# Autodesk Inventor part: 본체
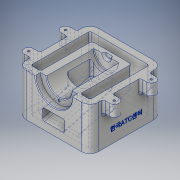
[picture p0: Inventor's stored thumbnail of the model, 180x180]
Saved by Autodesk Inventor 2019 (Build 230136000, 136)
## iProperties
Created: 2022-03
Part Number: 본체
Material: 알루미늄 6061
Document SubType Name: Modeling
Designer: LINE501-4
Density: 2.7 g/cm^3
Appearance: 알루미늄 - 평지
Mass: 1024.24 g
Surface Area: 844.702 cm^2
Volume: 379.349 cm^3
Author: LINE501-4
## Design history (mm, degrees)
sketch "스케치1"
  geometry: L1 (42, -55)-(-42, -55); L2 (-55, -42)-(-55, 42); L3 (-42, 55)-(42, 55); L4 (55, 42)-(55, -42); L5 (55, -55)-(-55, 55); L6 (-55, -55)-(55, 55); L7 (-42, -45)-(42, -45); L8 (45, -42)-(45, 42); L9 (-45, 42)-(-45, -42) reference; L10 (30, 0)-(30, 45); L11 (30, 45)-(30, -33); L12 (30, -33)-(-30, -33) reference; L13 (-30, -33)-(-30, 45) reference; L14 (42, 45)-(30, 45) reference; L15 (-30, 45)-(-42, 45) reference; A1 r 13 centre (42, -42) between (42, -55) and (55, -42); A2 r 13 centre (-42, -42) between (-55, -42) and (-42, -55); A3 r 13 centre (-42, 42) between (-42, 55) and (-55, 42); A4 r 13 centre (42, 42) between (55, 42) and (42, 55); A5 r 3 centre (42, -42) between (42, -45) and (45, -42); A6 r 3 centre (42, 42) between (45, 42) and (42, 45); A7 r 3 centre (-42, 42) between (-42, 45) and (-45, 42); A8 r 3 centre (-42, -42) between (-45, -42) and (-42, -45); 1 further point
  constraints: 30 end point, 16 point on circle, 8 centre point, 8 point on line, 8 tangent, 7 perpendicular, 5 parallel, 4 horizontal, 3 equal radius, 3 vertical, 2 midpoint, 5 other
  dimensions: "d0" = 110 distance of L5.end L6.end; "d1" = 110 distance of L6.start L5.end; "d2" = 13 radius of A1; "d3" = 10 distance between parallel lines of L1 L7; "d6" = 60 distance of L11.end L12.end
extrude "돌출1" new body sketch "스케치1" distance "d7" = 65; taper "d8" = 0 deg
sketch "스케치2"
  geometry: L1 (-55, -42)-(-55, 42) reference; L2 (-65, 21)-(-55, 21) reference; L3 (-65, 35)-(-55, 35); L4 (-65, -35)-(-55, -35) reference; L5 (-65, -21)-(-55, -21); L6 (55, -42)-(55, 42) reference; L7 (65, 21)-(55, 21) reference; L8 (65, 35)-(55, 35) reference; L9 (65, -21)-(55, -21) reference; L10 (65, -35)-(55, -35) reference; A1 r 13 centre (-42, 42) between (-42, 55) and (-55, 42) reference; A2 r 7 centre (-65, 28) between (-65, 35) and (-65, 21); A3 r 7 centre (-65, -28) between (-65, -21) and (-65, -35); A4 r 7 centre (65, -28) between (65, -35) and (65, -21); A5 r 7 centre (65, 28) between (65, 21) and (65, 35); 1 further point
  constraints: 16 end point, 8 point on circle, 8 point on line, 7 horizontal, 7 perpendicular, 4 centre point, 4 tangent, 4 other
  dimensions: "d13" = 14 diameter of A2; "d15" = 14 diameter of A3; "d18" = 14 diameter of A4; "d19" = 14 diameter of A5
extrude "돌출2" join sketch "스케치2" distance "d20" = 20; taper "d21" = 0 deg
sketch "스케치3"
  geometry: A1 r 7 centre (-65, 28) between (-65, 35) and (-65, 21) reference; A2 r 7 centre (-65, -28) between (-65, -21) and (-65, -35) reference; A3 r 7 centre (65, -28) between (65, -35) and (65, -21) reference; A4 r 7 centre (65, 28) between (65, 21) and (65, 35) reference; 5 further points
  constraints: 4 coincident
hole "구멍1" sketch "스케치3" at (-65, 28), (-65, -28), (65, -28), (65, 28) diameter "d22" = 3.242; stored, may be unused: countersink angle "d26" = 90 deg, drill point angle "d28" = 118 deg; dims "d23" = 9, "d24" = 4, "d25" = 2, "d27" = 11
sketch "스케치4"
  geometry: L1 (0, 65)-(84, 65) reference; L2 (34.5, 65)-(49.5, 65); C1 r 28 at (42, 65); C2 r 19 at (42, 65); A1 r 7.5 centre (42, 65) between (34.5, 65) and (49.5, 65); 1 further point
  constraints: 3 centre point, 2 coincident, 2 end point, 2 point on circle, 2 point on line, 1 midpoint
  dimensions: "d29" = 56 diameter of C1; "d30" = 38 diameter of C2; "d35" = 15 diameter of A1
extrude "돌출3" cut sketch "스케치4" distance "d31" = 8; taper "d32" = 0 deg
extrude "돌출4" cut sketch "스케치4" distance "d33" = 80; taper "d34" = 0 deg
extrude "돌출5" cut sketch "스케치4" distance "d36" = 84; taper "d37" = 0 deg
sketch "스케치5"
  geometry: L1 (65, -25)-(65, -29) reference; L2 (57.5, -25)-(57.5, -29) reference; L3 (57.5, -25)-(59.809, -29); L4 (57.5, -29)-(65, -29) reference; L5 (57.5, -25)-(62.119, -25); L6 (59.809, -29)-(57.5, -29); L7 (57.5, -29)-(57.5, -25); L8 (65, -25)-(65, -29); 1 further point
  constraints: 10 end point, 3 collinear, 1 equal length, 1 horizontal, 1 point on line
  dimensions: "d38" = 60 deg angle of L3 L5
revolve "회전1" sketch "스케치5" stored, may be unused: angle "d39" = 90 deg
extrude "돌출6" cut sketch "스케치4" distance "d40" = 84; taper "d41" = 0 deg
sketch "스케치7"
  geometry: L1 (42, -55)-(-42, -55) reference; L2 (0, -55)-(0, -19); L3 (0, -19)-(0, 0); L4 (-17, -19)-(17, -19); L5 (17, -19)-(17, 19); L6 (17, 19)-(-17, 19); L7 (-17, 19)-(-17, -19); L8 (-17, -19)-(17, 19); L9 (17, -19)-(-17, 19)
  constraints: 16 end point, 3 midpoint, 2 parallel, 1 collinear, 1 horizontal, 1 perpendicular, 1 vertical
  dimensions: "d44" = 36 distance of L2.start L2.end; "d45" = 19 distance of L2.end L3.end (derived); "d46" = 34 distance of L6.end L5.end; "d47" = 38 distance of L5.end L4.end
extrude "돌출7" cut sketch "스케치7" distance "d50" = 30; taper "d51" = 0 deg
sketch "스케치10"
  geometry: L1 (0, -33)-(65, -33) reference; L2 (0, -33)-(30, -33); L3 (30, -33)-(9.1, 45); L4 (31.425, -19)-(11.597, 55) reference; L5 (49.025, -19)-(29.197, 55); L6 (56.515, -19)-(35, -19) reference; L7 (56.515, -19)-(35, -19) reference; L8 (49.025, -19)-(31.425, -19); L9 (0, 55)-(65, 55) reference; L10 (0, 45)-(9.1, 45); L11 (0, 45)-(65, 45) reference; L12 (0, -33)-(0, 45) reference; L13 (0, -33)-(0, 45); 1 further point
  constraints: 14 end point, 6 point on line, 2 equal length, 1 other
  dimensions: "d59" = 30 distance of L1.start L2.end; "d60" = 75 deg angle of L3 L2; "d62" = 17 distance between parallel lines of L4 L5
extrude "돌출8" cut sketch "스케치10" stored distance "d63" = 34; taper "d64" = 0 deg
extrude "돌출9" cut sketch "스케치10" stored distance "d65" = 70; taper "d66" = 0 deg
sketch "스케치11"
  geometry: L1 (84, 65)-(0, 65) reference; 2 further points
  constraints: 1 other
hole "구멍2" sketch "스케치11" at (42, 42) diameter "d68" = 3.242; stored, may be unused: countersink angle "d72" = 90 deg, drill point angle "d74" = 118 deg; dims "d69" = 9, "d70" = 4, "d71" = 2, "d73" = 11
fillet "모깎기3" dims "d76" = 1
fillet "모깎기4" dims "d77" = 3
fillet "모깎기5" dims "d78" = 3
sketch "스케치12"
  geometry: L1 (84, 0)-(0, 0) reference; L2 (-13, 0)-(-13, 65) reference; 2 further points
  constraints: 1 other
  dimensions: "d79" = 20 distance from line of L1 point (42, 20); "d80" = 55 distance from line of L2 point (42, 20)
feature "엠보싱1" sketch "스케치12" dims "d0" = 110, "d1" = 110, "d2" = 13, "d3" = 10, "d6" = 60, "d81" = 0.5, "d82" = 0
chamfer "모따기1" distance "d83" = 1; stored, may be unused: second distance "d84" = 2, angle "d85" = 45 deg
chamfer "모따기2" distance "d86" = 1; stored, may be unused: second distance "d87" = 2, angle "d88" = 45 deg
fillet "모깎기7" dims "d90" = 3
fillet "모깎기9" dims "d92" = 3
node "솔리드1"
